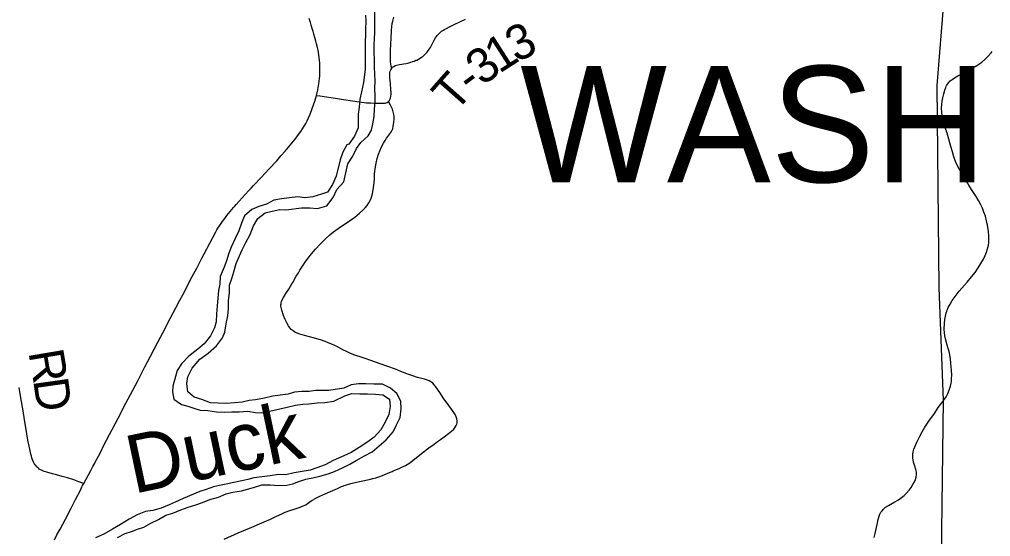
# Model space of a CAD drawing. Extents: x -10.5 to 40.6, y -3.2 to 22.
# Drawn here: x -7.693 to -6.111, y 16.014 to 16.857 of the extents above; entities that cross this region are included whole.
import ezdxf

# ---------------------------------------------------------------- set-up
doc = ezdxf.new("R2010")
doc.units = 0
for name, color, linetype in [('GM_X_County_Text', 7, 'Continuous'), ('GM_X_Major_River', 7, 'Continuous'), ('GM_X_Major_River_Text', 7, 'Continuous'), ('GM_X_State_Route', 7, 'Continuous'), ('GM_X_Township_Road', 7, 'Continuous'), ('GM_X_Township_Road_Text', 7, 'Continuous'), ('GM_X_Township_Text', 7, 'Continuous')]:
    doc.layers.add(name, color=color, linetype=linetype)

msp = doc.modelspace()

# ---------------------------------------------------------------- linework, layer by layer
at = {"layer": 'GM_X_Major_River'}
for points in [[(-7.1756, 16.5797), (-7.1646, 16.5923), (-7.1624, 16.6022), (-7.1599, 16.6121), (-7.1577, 16.6216), (-7.1498, 16.6342), (-7.1435, 16.6468), (-7.1368, 16.6564), (-7.1247, 16.6671), (-7.1195, 16.6767), (-7.1173, 16.6866), (-7.1148, 16.6987), (-7.1145, 16.7113), (-7.1135, 16.7215), (-7.1132, 16.731), (-7.1137, 16.7454), (-7.1134, 16.7557), (-7.1139, 16.769), (-7.1144, 16.7788), (-7.1147, 16.8157), (-7.1144, 16.8252), (-7.1141, 16.8358), (-7.1139, 16.8472), (-7.1141, 16.8726)], [(-7.1292, 16.8641), (-7.1284, 16.8539), (-7.129, 16.8413), (-7.1293, 16.8311), (-7.1296, 16.8212), (-7.1295, 16.811), (-7.1297, 16.7973), (-7.1295, 16.7756), (-7.1324, 16.7544), (-7.1356, 16.7391), (-7.1382, 16.727), (-7.1396, 16.714), (-7.141, 16.7026), (-7.1409, 16.6897), (-7.1412, 16.6802), (-7.1471, 16.6669), (-7.1561, 16.6535)], [(-7.1561, 16.6535), (-7.1595, 16.6527), (-7.1658, 16.6405), (-7.1706, 16.6283), (-7.177, 16.6017)], [(-7.177, 16.6017), (-7.1829, 16.5879), (-7.1907, 16.5757), (-7.2009, 16.5721), (-7.2149, 16.5681), (-7.2277, 16.5665), (-7.2395, 16.5678), (-7.2528, 16.5665), (-7.266, 16.5648), (-7.2781, 16.5627), (-7.2905, 16.5561), (-7.303, 16.5522), (-7.3143, 16.5471), (-7.3263, 16.5371), (-7.3303, 16.5264), (-7.3354, 16.5123), (-7.3413, 16.5001), (-7.3476, 16.4859), (-7.3516, 16.476), (-7.3552, 16.4635), (-7.3593, 16.4532), (-7.3659, 16.4379), (-7.3661, 16.4254), (-7.3682, 16.4155), (-7.3696, 16.4026), (-7.3706, 16.3904), (-7.3719, 16.3771), (-7.3725, 16.3642), (-7.375, 16.3543), (-7.3813, 16.3414), (-7.3917, 16.3287), (-7.4022, 16.3195), (-7.4168, 16.3083), (-7.4288, 16.2956), (-7.4355, 16.2849), (-7.4387, 16.2754), (-7.4427, 16.2597), (-7.4433, 16.2503), (-7.4413, 16.2381), (-7.4286, 16.2296), (-7.4184, 16.2271), (-7.4085, 16.2234), (-7.3982, 16.2201), (-7.3857, 16.2199), (-7.3716, 16.2179), (-7.358, 16.2169), (-7.3466, 16.2174), (-7.3348, 16.2176), (-7.3208, 16.2185), (-7.3083, 16.2168), (-7.2977, 16.2162), (-7.2825, 16.2191), (-7.2568, 16.2255), (-7.2429, 16.2287), (-7.2311, 16.23), (-7.2213, 16.2309), (-7.2077, 16.2322), (-7.1952, 16.2331), (-7.1808, 16.2349), (-7.1629, 16.2438)], [(-7.1641, 16.2563), (-7.1886, 16.2526), (-7.2106, 16.2523), (-7.2208, 16.251), (-7.2329, 16.2508), (-7.2447, 16.2495), (-7.2549, 16.2467), (-7.2681, 16.2447), (-7.2798, 16.243), (-7.2934, 16.2401), (-7.3082, 16.2373), (-7.3184, 16.236), (-7.3297, 16.2336), (-7.3426, 16.2323), (-7.3559, 16.231), (-7.3688, 16.2319), (-7.3813, 16.2325), (-7.3958, 16.238), (-7.408, 16.2413), (-7.4183, 16.2502), (-7.42, 16.2638), (-7.4186, 16.2749), (-7.4113, 16.289), (-7.3986, 16.3032), (-7.3854, 16.3132), (-7.3716, 16.3252), (-7.3619, 16.3382), (-7.3582, 16.3477), (-7.3561, 16.361), (-7.3533, 16.374), (-7.3523, 16.3861), (-7.3521, 16.3983), (-7.3508, 16.4119), (-7.3505, 16.4241), (-7.3469, 16.4348), (-7.3436, 16.4458), (-7.3396, 16.4595), (-7.3341, 16.4717), (-7.3297, 16.4813), (-7.3242, 16.4935), (-7.3168, 16.5068), (-7.3113, 16.5206), (-7.3042, 16.5324), (-7.2926, 16.5417), (-7.2813, 16.5445), (-7.2684, 16.5473), (-7.2589, 16.5467), (-7.2332, 16.5501), (-7.2199, 16.5499), (-7.2074, 16.5489), (-7.1923, 16.5533), (-7.1815, 16.5667), (-7.1756, 16.5797)], [(-7.1652, 16.1272), (-7.1546, 16.1326), (-7.1445, 16.1384), (-7.1309, 16.1458), (-7.118, 16.1524), (-7.1067, 16.1623), (-7.0954, 16.1719), (-7.0842, 16.1853), (-7.079, 16.1953), (-7.0726, 16.2082), (-7.0712, 16.2223), (-7.0717, 16.2348), (-7.0779, 16.2473), (-7.0883, 16.2563), (-7.1016, 16.2626), (-7.1153, 16.2629), (-7.1285, 16.2635), (-7.1407, 16.263), (-7.1524, 16.2614), (-7.1641, 16.2563)], [(-7.1629, 16.2438), (-7.1515, 16.2473), (-7.1383, 16.2471), (-7.1257, 16.2472), (-7.1128, 16.2462), (-7.1011, 16.2452), (-7.09, 16.2381), (-7.0891, 16.2263), (-7.0913, 16.2134), (-7.0972, 16.2008), (-7.1043, 16.1882), (-7.1152, 16.1763), (-7.1254, 16.1686), (-7.1393, 16.1594), (-7.1522, 16.1516), (-7.1643, 16.1462)], [(-7.1643, 16.1462), (-7.1817, 16.1381), (-7.1949, 16.1311), (-7.2085, 16.1264), (-7.219, 16.1224), (-7.2455, 16.1183), (-7.2588, 16.1151), (-7.2709, 16.1153), (-7.2845, 16.1136), (-7.311, 16.1102), (-7.3208, 16.1074), (-7.3307, 16.105), (-7.3435, 16.1025), (-7.356, 16.0997), (-7.3666, 16.0977), (-7.3768, 16.0953), (-7.3888, 16.0909), (-7.3987, 16.0881), (-7.4258, 16.0764), (-7.439, 16.0705), (-7.4488, 16.0662), (-7.4616, 16.0607), (-7.4752, 16.0571), (-7.4873, 16.0555), (-7.5009, 16.05), (-7.5137, 16.043), (-7.528, 16.0341), (-7.5411, 16.0267), (-7.5554, 16.0181), (-7.569, 16.0126)], [(-7.533, 16.0131), (-7.5202, 16.0194), (-7.51, 16.0225), (-7.5002, 16.0265), (-7.49, 16.03), (-7.4787, 16.0362), (-7.4663, 16.0425), (-7.4542, 16.0491), (-7.4429, 16.0527), (-7.4297, 16.0578), (-7.4177, 16.0625), (-7.4052, 16.0664), (-7.3943, 16.07), (-7.3826, 16.0747), (-7.3682, 16.0787), (-7.3561, 16.0838), (-7.3452, 16.0866), (-7.3308, 16.0891), (-7.321, 16.0915), (-7.3112, 16.0943), (-7.298, 16.0986), (-7.2843, 16.0988), (-7.2703, 16.0975), (-7.2574, 16.0984), (-7.2476, 16.1001), (-7.2378, 16.104), (-7.2261, 16.1079), (-7.2151, 16.11), (-7.2034, 16.1128), (-7.1898, 16.1164), (-7.1796, 16.1203), (-7.1652, 16.1272)]]:
    msp.add_lwpolyline(points, dxfattribs=at)
at = {"layer": 'GM_X_State_Route'}
for points in [[(-7.3918, 16.4752), (-7.3826, 16.4926), (-7.3728, 16.5107), (-7.3711, 16.5139), (-7.3694, 16.5166), (-7.3669, 16.5207), (-7.3643, 16.5246), (-7.3623, 16.5274), (-7.36, 16.5306), (-7.3571, 16.5345), (-7.3547, 16.5375), (-7.3519, 16.541), (-7.3494, 16.544), (-7.3468, 16.5472), (-7.3442, 16.5503), (-7.342, 16.5528), (-7.3397, 16.5554), (-7.3349, 16.5607), (-7.3298, 16.5662), (-7.3249, 16.5717), (-7.3189, 16.578), (-7.3151, 16.5822), (-7.3115, 16.5862), (-7.2986, 16.5999), (-7.2863, 16.6131), (-7.2737, 16.6268), (-7.2667, 16.6345), (-7.2601, 16.6421), (-7.2519, 16.6519), (-7.2436, 16.6621), (-7.2399, 16.6671), (-7.2345, 16.6746), (-7.2291, 16.6828), (-7.2264, 16.6873), (-7.2241, 16.6916), (-7.2217, 16.6967), (-7.2191, 16.7027), (-7.2157, 16.712), (-7.2117, 16.7238), (-7.209, 16.7329), (-7.2068, 16.7423), (-7.205, 16.752), (-7.2044, 16.7566), (-7.204, 16.7606), (-7.2036, 16.7646), (-7.2035, 16.768), (-7.2033, 16.7725), (-7.2033, 16.7772), (-7.2034, 16.7815), (-7.2036, 16.7858), (-7.204, 16.7904), (-7.2044, 16.7944), (-7.2049, 16.7991), (-7.2056, 16.8031), (-7.2063, 16.8069), (-7.2073, 16.8114), (-7.2086, 16.8172), (-7.2098, 16.8216), (-7.2114, 16.8276), (-7.213, 16.8331), (-7.2142, 16.8371), (-7.2158, 16.8424), (-7.2175, 16.8477), (-7.2188, 16.8519), (-7.2207, 16.8583)], [(-7.6356, 16.0089), (-7.6315, 16.017), (-7.6264, 16.0266), (-7.6178, 16.0428), (-7.6082, 16.0609), (-7.6013, 16.0748), (-7.5934, 16.0902), (-7.5909, 16.0952), (-7.5897, 16.0974), (-7.5879, 16.1008), (-7.5803, 16.1148), (-7.5765, 16.1219), (-7.573, 16.1285), (-7.57, 16.134), (-7.568, 16.1378), (-7.564, 16.1455), (-7.5603, 16.1527), (-7.5549, 16.1632), (-7.5326, 16.2062), (-7.5192, 16.232), (-7.512, 16.2458), (-7.5005, 16.2671), (-7.4948, 16.2781), (-7.492, 16.2836), (-7.4883, 16.2907), (-7.484, 16.299), (-7.4791, 16.3083), (-7.4671, 16.3314), (-7.4631, 16.3392), (-7.4593, 16.3463), (-7.4469, 16.3699), (-7.4378, 16.3869), (-7.4312, 16.3996), (-7.4266, 16.4084), (-7.4111, 16.4381), (-7.4039, 16.4519), (-7.3957, 16.4679), (-7.3918, 16.4752)]]:
    msp.add_lwpolyline(points, dxfattribs=at)
at = {"layer": 'GM_X_Township_Road'}
for points in [[(-7.0864, 16.7773), (-7.0873, 16.7809), (-7.088, 16.7841), (-7.0885, 16.7884), (-7.0885, 16.7934), (-7.0885, 16.7971), (-7.0883, 16.8008), (-7.0882, 16.8058), (-7.0878, 16.8169), (-7.0874, 16.8257), (-7.0868, 16.8393), (-7.0863, 16.8449), (-7.0855, 16.8504), (-7.0846, 16.8539), (-7.0827, 16.8604)], [(-7.0864, 16.7773), (-7.0849, 16.779), (-7.0829, 16.7805), (-7.0807, 16.7817), (-7.0784, 16.7824), (-7.0736, 16.7835), (-7.07, 16.7841), (-7.067, 16.7845), (-7.0626, 16.7854), (-7.0585, 16.7863), (-7.055, 16.7873), (-7.0526, 16.7882), (-7.0497, 16.7891), (-7.0469, 16.7903), (-7.0457, 16.7908), (-7.0429, 16.7921), (-7.0398, 16.794), (-7.0377, 16.7954), (-7.0357, 16.7968), (-7.0324, 16.7996), (-7.0306, 16.8013), (-7.0286, 16.8036), (-7.0263, 16.8066), (-7.0246, 16.8091), (-7.0234, 16.8112), (-7.0221, 16.8136), (-7.0185, 16.8208), (-7.0174, 16.823), (-7.0149, 16.8272), (-7.0135, 16.8293), (-7.0124, 16.8308), (-7.0099, 16.8335), (-7.0072, 16.8361), (-7.0053, 16.8377), (-7.0022, 16.8397), (-7.0001, 16.841), (-6.9974, 16.8424), (-6.9923, 16.8449), (-6.9867, 16.8475), (-6.9733, 16.8539), (-6.966, 16.8573)], [(-6.1833, 16.7482), (-6.1829, 16.7492), (-6.1826, 16.7497), (-6.1798, 16.7537), (-6.177, 16.7567), (-6.174, 16.7591), (-6.1702, 16.7617), (-6.1648, 16.7649), (-6.157, 16.7691), (-6.1469, 16.7741), (-6.1334, 16.7819), (-6.1255, 16.7875), (-6.1207, 16.7918), (-6.1154, 16.797), (-6.1103, 16.8024), (-6.1085, 16.8045)], [(-7.0914, 16.7233), (-7.09, 16.7249), (-7.0892, 16.7266), (-7.0883, 16.7289), (-7.0876, 16.7319), (-7.0874, 16.7353), (-7.0874, 16.7381), (-7.0877, 16.743), (-7.0883, 16.7523), (-7.0892, 16.7616), (-7.0894, 16.7672), (-7.0892, 16.7703), (-7.0887, 16.7727), (-7.0878, 16.775), (-7.0864, 16.7773)], [(-6.1829, 16.6745), (-6.1832, 16.6756), (-6.1834, 16.6762), (-6.185, 16.6809), (-6.1878, 16.6891), (-6.1893, 16.6944), (-6.1903, 16.6999), (-6.1908, 16.7061), (-6.1909, 16.7123), (-6.1906, 16.7184), (-6.1899, 16.724), (-6.189, 16.7292), (-6.1874, 16.7358), (-6.1859, 16.7419), (-6.1843, 16.7463), (-6.1833, 16.7482)], [(-7.209, 16.7329), (-7.2036, 16.7322), (-7.1926, 16.7308), (-7.1858, 16.7298), (-7.1779, 16.7285), (-7.165, 16.7265), (-7.1503, 16.7242), (-7.1392, 16.7226), (-7.1275, 16.7212), (-7.1232, 16.7209), (-7.1207, 16.7208), (-7.1152, 16.7207), (-7.1003, 16.7203), (-7.0972, 16.7205), (-7.0953, 16.7209), (-7.0936, 16.7216), (-7.0914, 16.7233)], [(-7.3591, 16.0101), (-7.3365, 16.0204), (-7.3181, 16.0279), (-7.2942, 16.0384), (-7.284, 16.0429), (-7.2739, 16.0477), (-7.2654, 16.0517), (-7.2597, 16.0541), (-7.2522, 16.057), (-7.2469, 16.0588), (-7.2369, 16.062), (-7.2328, 16.0635), (-7.2305, 16.0644), (-7.2265, 16.0663), (-7.2235, 16.0684), (-7.2157, 16.0736), (-7.2134, 16.0751), (-7.2119, 16.076), (-7.2099, 16.077), (-7.2032, 16.0804), (-7.1936, 16.0847), (-7.1748, 16.0929), (-7.1714, 16.0944), (-7.1681, 16.0958), (-7.1661, 16.0966), (-7.164, 16.0975), (-7.1619, 16.0982), (-7.1599, 16.0988), (-7.1567, 16.0999), (-7.151, 16.1014), (-7.1438, 16.1033), (-7.1359, 16.1049), (-7.1231, 16.1074), (-7.1171, 16.1088), (-7.1123, 16.1102), (-7.1076, 16.1118), (-7.1012, 16.1142), (-7.0927, 16.1179), (-7.0858, 16.1207), (-7.084, 16.1214), (-7.0742, 16.1252), (-7.0686, 16.1278), (-7.0637, 16.1304), (-7.0585, 16.1337), (-7.0521, 16.1385), (-7.0351, 16.1518), (-7.0258, 16.1589), (-7.0173, 16.1652), (-7.0118, 16.1692), (-7.0088, 16.1714), (-7.0069, 16.1728), (-6.9989, 16.1787), (-6.9959, 16.1809), (-6.9891, 16.1863), (-6.9854, 16.1896), (-6.983, 16.1925), (-6.9815, 16.1952), (-6.9806, 16.1975), (-6.98, 16.1999), (-6.9798, 16.2029), (-6.9801, 16.206), (-6.9812, 16.2096), (-6.9832, 16.2134), (-6.9864, 16.218), (-6.9962, 16.2315), (-7.0013, 16.2387), (-7.0082, 16.2489), (-7.0144, 16.2583), (-7.0171, 16.2617), (-7.0197, 16.2644), (-7.0211, 16.2656), (-7.0226, 16.2666), (-7.0254, 16.2681), (-7.0282, 16.2693), (-7.033, 16.2707), (-7.0444, 16.2738), (-7.0521, 16.2763), (-7.062, 16.2798), (-7.0713, 16.2835), (-7.0805, 16.2871), (-7.105, 16.296), (-7.1204, 16.3011), (-7.1297, 16.3043), (-7.1362, 16.3065), (-7.1379, 16.3072), (-7.1432, 16.309), (-7.1479, 16.3106), (-7.1558, 16.314), (-7.1598, 16.3158), (-7.1659, 16.3188), (-7.1736, 16.3229), (-7.1803, 16.3262), (-7.187, 16.3292), (-7.1945, 16.3323), (-7.2026, 16.3351), (-7.2121, 16.3378), (-7.2282, 16.342), (-7.2359, 16.3442), (-7.2406, 16.3459), (-7.2439, 16.3475), (-7.247, 16.3494), (-7.2499, 16.3518), (-7.2525, 16.3545), (-7.2546, 16.3575), (-7.2568, 16.3613), (-7.2599, 16.3681), (-7.2624, 16.3744), (-7.2653, 16.3833), (-7.2665, 16.3874), (-7.2668, 16.3899), (-7.2667, 16.3923), (-7.2666, 16.3933), (-7.2663, 16.395), (-7.2658, 16.3973), (-7.2647, 16.4002), (-7.2627, 16.404), (-7.2586, 16.4102), (-7.2538, 16.4174), (-7.251, 16.4222), (-7.2488, 16.426), (-7.2476, 16.4281), (-7.2418, 16.4384), (-7.2384, 16.4443), (-7.2359, 16.4486), (-7.2329, 16.4533), (-7.2273, 16.4616), (-7.223, 16.4676), (-7.2172, 16.4749), (-7.2103, 16.4829), (-7.2022, 16.4915), (-7.1939, 16.4998), (-7.187, 16.5061), (-7.1812, 16.5107), (-7.1736, 16.5162), (-7.1551, 16.5288), (-7.1466, 16.535), (-7.1389, 16.5412), (-7.1333, 16.5462), (-7.1294, 16.5502), (-7.1263, 16.554), (-7.1235, 16.5582), (-7.1215, 16.562), (-7.1198, 16.566), (-7.1182, 16.5707), (-7.117, 16.5762), (-7.1158, 16.5829), (-7.1149, 16.5909), (-7.1145, 16.5977), (-7.1143, 16.6051), (-7.1139, 16.6095), (-7.1135, 16.6132), (-7.113, 16.6169), (-7.1118, 16.6229), (-7.11, 16.6302), (-7.1078, 16.6373), (-7.1054, 16.6437), (-7.1035, 16.6483), (-7.0998, 16.6555), (-7.0972, 16.6597), (-7.0947, 16.6633), (-7.0925, 16.6663), (-7.0879, 16.6729), (-7.0858, 16.6767), (-7.0848, 16.6789), (-7.0838, 16.6828), (-7.0829, 16.689), (-7.0824, 16.6942), (-7.0824, 16.698), (-7.0829, 16.7023), (-7.0838, 16.7065), (-7.0851, 16.7107), (-7.0871, 16.7152), (-7.0883, 16.7174), (-7.0914, 16.7233)], [(-6.1827, 16.3815), (-6.1824, 16.3823), (-6.1821, 16.3833), (-6.1802, 16.3878), (-6.1773, 16.3933), (-6.1737, 16.3991), (-6.169, 16.4057), (-6.1624, 16.414), (-6.1494, 16.429), (-6.1422, 16.4375), (-6.1365, 16.4449), (-6.1312, 16.4525), (-6.1269, 16.4594), (-6.1229, 16.4664), (-6.1199, 16.4725), (-6.1178, 16.4777), (-6.1161, 16.483), (-6.1148, 16.489), (-6.1142, 16.4933), (-6.114, 16.4983), (-6.1141, 16.5039), (-6.1148, 16.5113), (-6.1163, 16.5217), (-6.1178, 16.529), (-6.1197, 16.5362), (-6.122, 16.5432), (-6.1246, 16.5496), (-6.1275, 16.5557), (-6.1307, 16.5617), (-6.1349, 16.5687), (-6.1423, 16.5801), (-6.1467, 16.5869), (-6.149, 16.5906), (-6.1537, 16.5978), (-6.1586, 16.6057), (-6.1621, 16.6122), (-6.1651, 16.6183), (-6.1683, 16.6257), (-6.1711, 16.6333), (-6.1735, 16.641), (-6.1759, 16.65), (-6.1791, 16.662), (-6.1819, 16.6715), (-6.1829, 16.6745)], [(-6.1859, 16.3417), (-6.1865, 16.3465), (-6.1868, 16.3521), (-6.1865, 16.3614), (-6.1858, 16.3682), (-6.1849, 16.3737), (-6.1835, 16.3791), (-6.1827, 16.3815)], [(-6.1887, 16.2352), (-6.1881, 16.2361), (-6.1838, 16.2419), (-6.1819, 16.2451), (-6.1809, 16.2473), (-6.1782, 16.2545), (-6.1767, 16.2595), (-6.1756, 16.2645), (-6.1751, 16.2677), (-6.1747, 16.272), (-6.1746, 16.2775), (-6.1749, 16.2854), (-6.1758, 16.2965), (-6.1767, 16.3044), (-6.1775, 16.3092), (-6.1777, 16.3105), (-6.1789, 16.3159), (-6.1802, 16.3207), (-6.1818, 16.326), (-6.1848, 16.3368), (-6.1859, 16.3417)], [(-7.5879, 16.1008), (-7.5958, 16.1037), (-7.6041, 16.1066), (-7.6146, 16.11), (-7.6229, 16.1125), (-7.6325, 16.115), (-7.6385, 16.1166), (-7.648, 16.1194), (-7.6521, 16.1207), (-7.6545, 16.1216), (-7.6566, 16.1224), (-7.6585, 16.1234), (-7.6602, 16.1245), (-7.6617, 16.1257), (-7.663, 16.1269), (-7.6645, 16.1283), (-7.6656, 16.1295), (-7.6669, 16.1312), (-7.6684, 16.1336), (-7.6695, 16.1357), (-7.6713, 16.1396), (-7.6723, 16.1425), (-7.6732, 16.1454), (-7.6741, 16.1485), (-7.6759, 16.157), (-7.6787, 16.1715), (-7.6823, 16.1923), (-7.6843, 16.2045), (-7.6865, 16.2192), (-7.6902, 16.2404), (-7.693, 16.2574)], [(-6.3008, 16.0129), (-6.2993, 16.0193), (-6.2961, 16.0339), (-6.2942, 16.0424), (-6.2927, 16.0478), (-6.2913, 16.0512), (-6.2898, 16.054), (-6.288, 16.0565), (-6.2856, 16.0593), (-6.2823, 16.0622), (-6.2773, 16.0651), (-6.2673, 16.0709), (-6.2614, 16.0744), (-6.2563, 16.0779), (-6.252, 16.0815), (-6.248, 16.0854), (-6.2439, 16.0901), (-6.2406, 16.0946), (-6.2376, 16.0993), (-6.2352, 16.1037), (-6.2334, 16.1076), (-6.2323, 16.1111), (-6.2316, 16.1155), (-6.2318, 16.1193), (-6.2327, 16.1239), (-6.2344, 16.1294), (-6.2365, 16.1359), (-6.2375, 16.1393), (-6.2379, 16.1421), (-6.238, 16.1452), (-6.2379, 16.1488), (-6.2373, 16.1525), (-6.2361, 16.1566), (-6.2342, 16.1619), (-6.2315, 16.1681), (-6.2277, 16.1759), (-6.2226, 16.1852), (-6.2181, 16.1926), (-6.2116, 16.2024), (-6.2028, 16.2152), (-6.1966, 16.2245), (-6.1887, 16.2352)]]:
    msp.add_lwpolyline(points, dxfattribs=at)
at = {"layer": 'GM_X_Township_Text'}
msp.add_lwpolyline([(-6.1874, 16.891), (-6.1985, 16.7494), (-6.1956, 16.4198), (-6.1883, 16.2366), (-6.1993, 15.3843), (-6.2122, 14.1), (-3.7445, 14.1), (-3.7445, 16.8499)], dxfattribs=at)

# ---------------------------------------------------------------- texts
at = {"layer": 'GM_X_County_Text'}
msp.add_text('WASHINGTON COUNTY', height=0.189394, dxfattribs=at).set_placement((-6.8771, 16.5918))
at = {"layer": 'GM_X_Major_River_Text'}
msp.add_text('Duck', height=0.0947, rotation=11.9039, dxfattribs=at).set_placement((-7.5071, 16.0838))
at = {"layer": 'GM_X_Township_Road_Text'}
for s, rotation, p in [('3', 26.0856, (-6.8834, 16.786)), ('1', 32.6855, (-6.9114, 16.768)), ('3', 36.8699, (-6.9385, 16.7476)), ('T', 48.5601, (-6.983, 16.7038)), ('-', 36.9698, (-6.9571, 16.7336)), ('R', 279.6587, (-7.6781, 16.315)), ('D', 278.0992, (-7.6704, 16.2694))]:
    msp.add_text(s, height=0.0568, rotation=rotation, dxfattribs=at).set_placement(p)

doc.saveas('drawing.dxf')
